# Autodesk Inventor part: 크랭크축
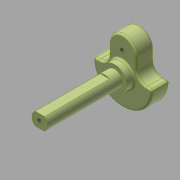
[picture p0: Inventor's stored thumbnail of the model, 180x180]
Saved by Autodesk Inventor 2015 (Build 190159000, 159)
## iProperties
Created: 2018-01
Part Number: 크랭크축
Material: 강철, 탄소
Document SubType Name: Modeling
Designer: mduedu
Density: 7.87 g/cm^3
Appearance: 아연 크롬산색 2
Mass: 57.3416 g
Surface Area: 32.1344 cm^2
Volume: 7.2861 cm^3
Author: mduedu
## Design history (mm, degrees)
sketch "스케치1"
  geometry: L1 (-15, 0)-(15, 0); L2 (-7, 0)-(7, 0); L3 (7, 0)-(7, 10); L4 (-7, 10)-(-7, 0); A1 r 15 centre (0, 0) between (-15, 0) and (15, 0); A2 r 7 centre (0, 10) between (7, 10) and (-7, 10); 3 further points
  constraints: 8 end point, 4 point on circle, 3 coincident, 2 centre point, 2 horizontal, 2 midpoint, 2 tangent, 1 parallel, 1 perpendicular, 1 point on line
  dimensions: "d0" = 30 diameter of A1; "d1" = 17 dimension on A2 L1; "d2" = 7 radius of A2
extrude "돌출1" new body sketch "스케치1" distance "d4" = 9; taper "d5" = 0 deg
sketch "스케치2"
  geometry: C1 r 6 at (0, 0); 1 further point
  constraints: 1 centre point, 1 coincident
  dimensions: "d6" = 12 diameter of C1
extrude "돌출2" join sketch "스케치2" distance "d7" = 4; taper "d8" = 0 deg
sketch "스케치3"
  geometry: C1 r 4 at (0, 0); 1 further point
  constraints: 1 centre point, 1 coincident
  dimensions: "d9" = 8 diameter of C1
extrude "돌출3" join sketch "스케치3" distance "d10" = 38; taper "d11" = 0 deg
sketch "스케치4"
  geometry: L1 (-2.332, 3.25)-(2.332, 3.25); L2 (-2.332, -3.25)-(2.332, -3.25); A1 r 4 centre (0, 0) between (-2.332, 3.25) and (2.332, 3.25) reference; A2 r 4 centre (0, 0) between (2.332, 3.25) and (-2.332, 3.25); A3 r 4 centre (0, 0) between (-2.332, -3.25) and (2.332, -3.25); 1 further point
  constraints: 8 point on circle, 4 end point, 2 centre point, 2 coincident, 2 parallel, 1 horizontal
  dimensions: "d12" = 6.5 distance between parallel lines of L2 L1
extrude "돌출4" cut sketch "스케치4" distance "d13" = 33; taper "d14" = 0 deg
fillet "모깎기1" dims "d15" = 5
fillet "모깎기2" dims "d16" = 1
fillet "모깎기3" dims "d17" = 1
fillet "모깎기4" dims "d18" = 1
sketch "스케치5"
  geometry: 1 further point
  constraints: 1 other
hole "구멍1" sketch "스케치5" at (0, 10) diameter "d19" = 2.459; stored, may be unused: countersink angle "d23" = 90 deg, drill point angle "d25" = 120 deg; dims "d20" = 10, "d21" = 4, "d22" = 2, "d24" = 11.5
sketch "스케치6"
  geometry: 1 further point
  constraints: 1 other
hole "구멍2" sketch "스케치6" at (0, 0) diameter "d26" = 2.459; stored, may be unused: countersink angle "d30" = 90 deg, drill point angle "d32" = 120 deg; dims "d27" = 12.7, "d28" = 4, "d29" = 2, "d31" = 14.2
node "솔리드1"
node "투영된 루프1"
